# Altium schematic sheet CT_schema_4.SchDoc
size 604 x 419 mm
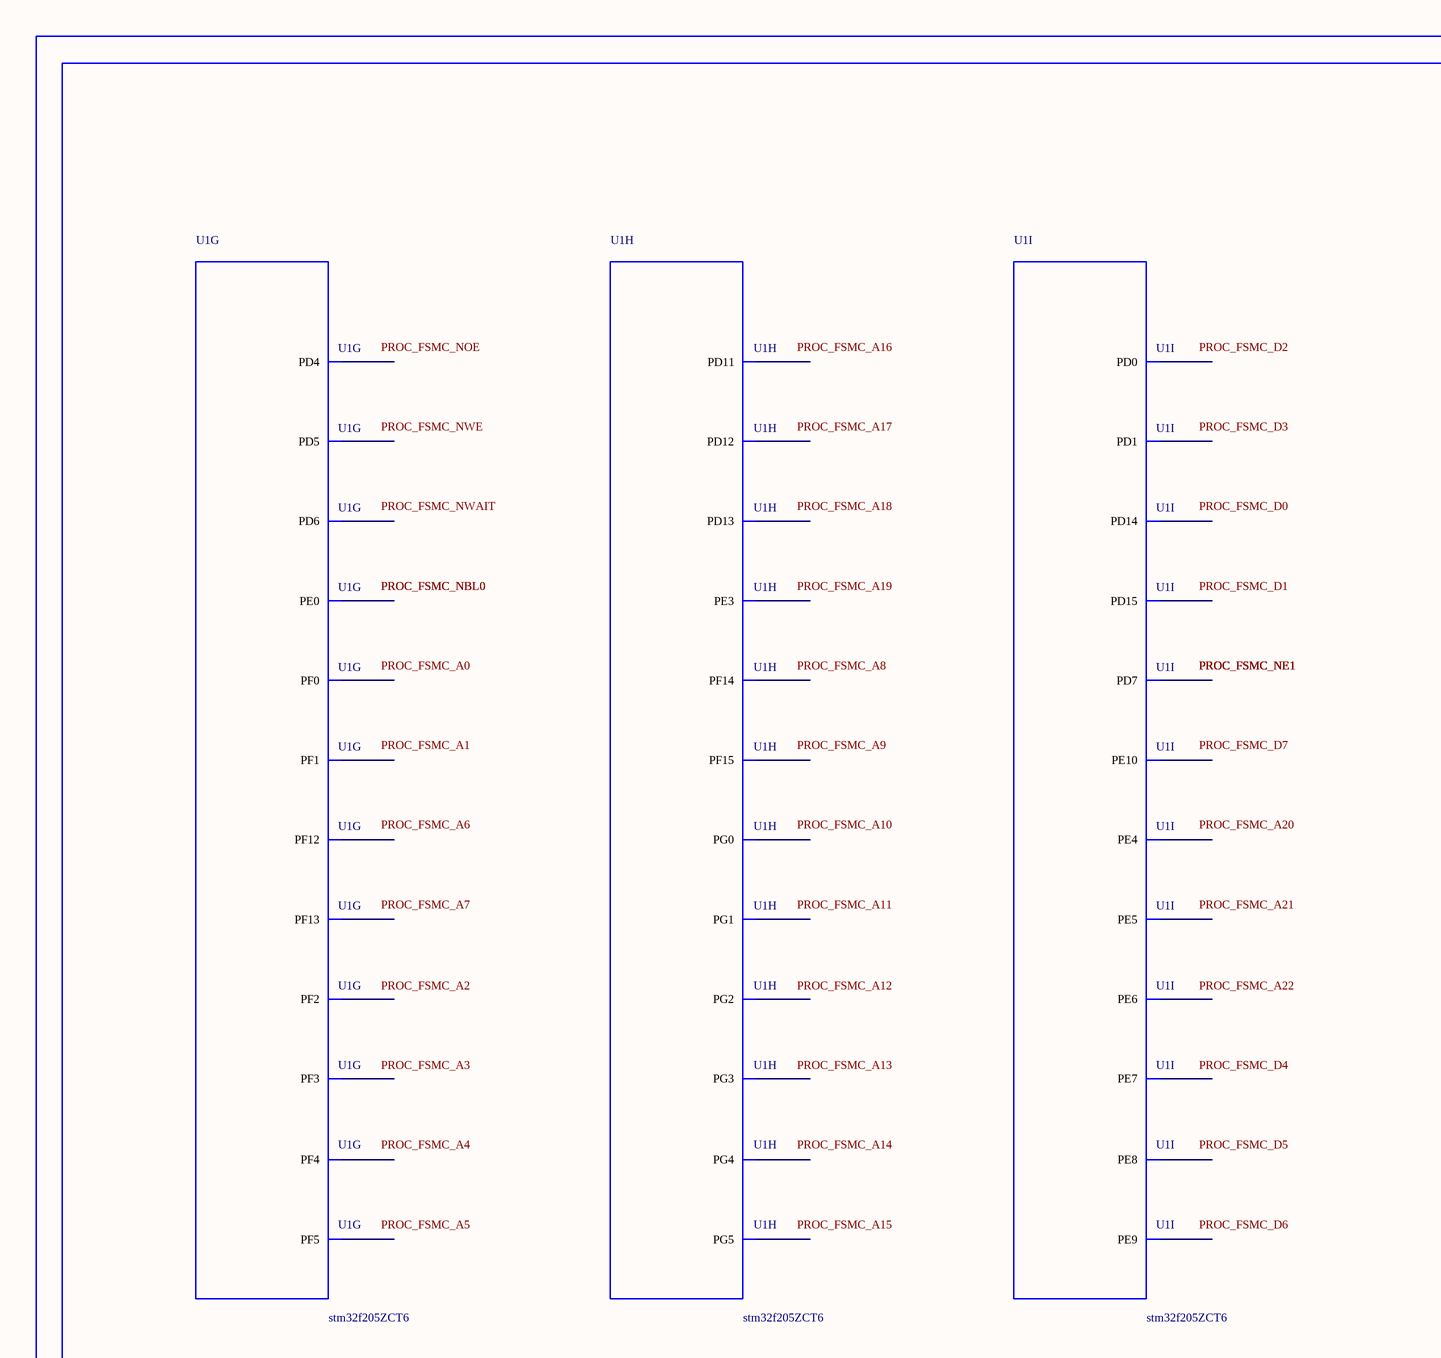
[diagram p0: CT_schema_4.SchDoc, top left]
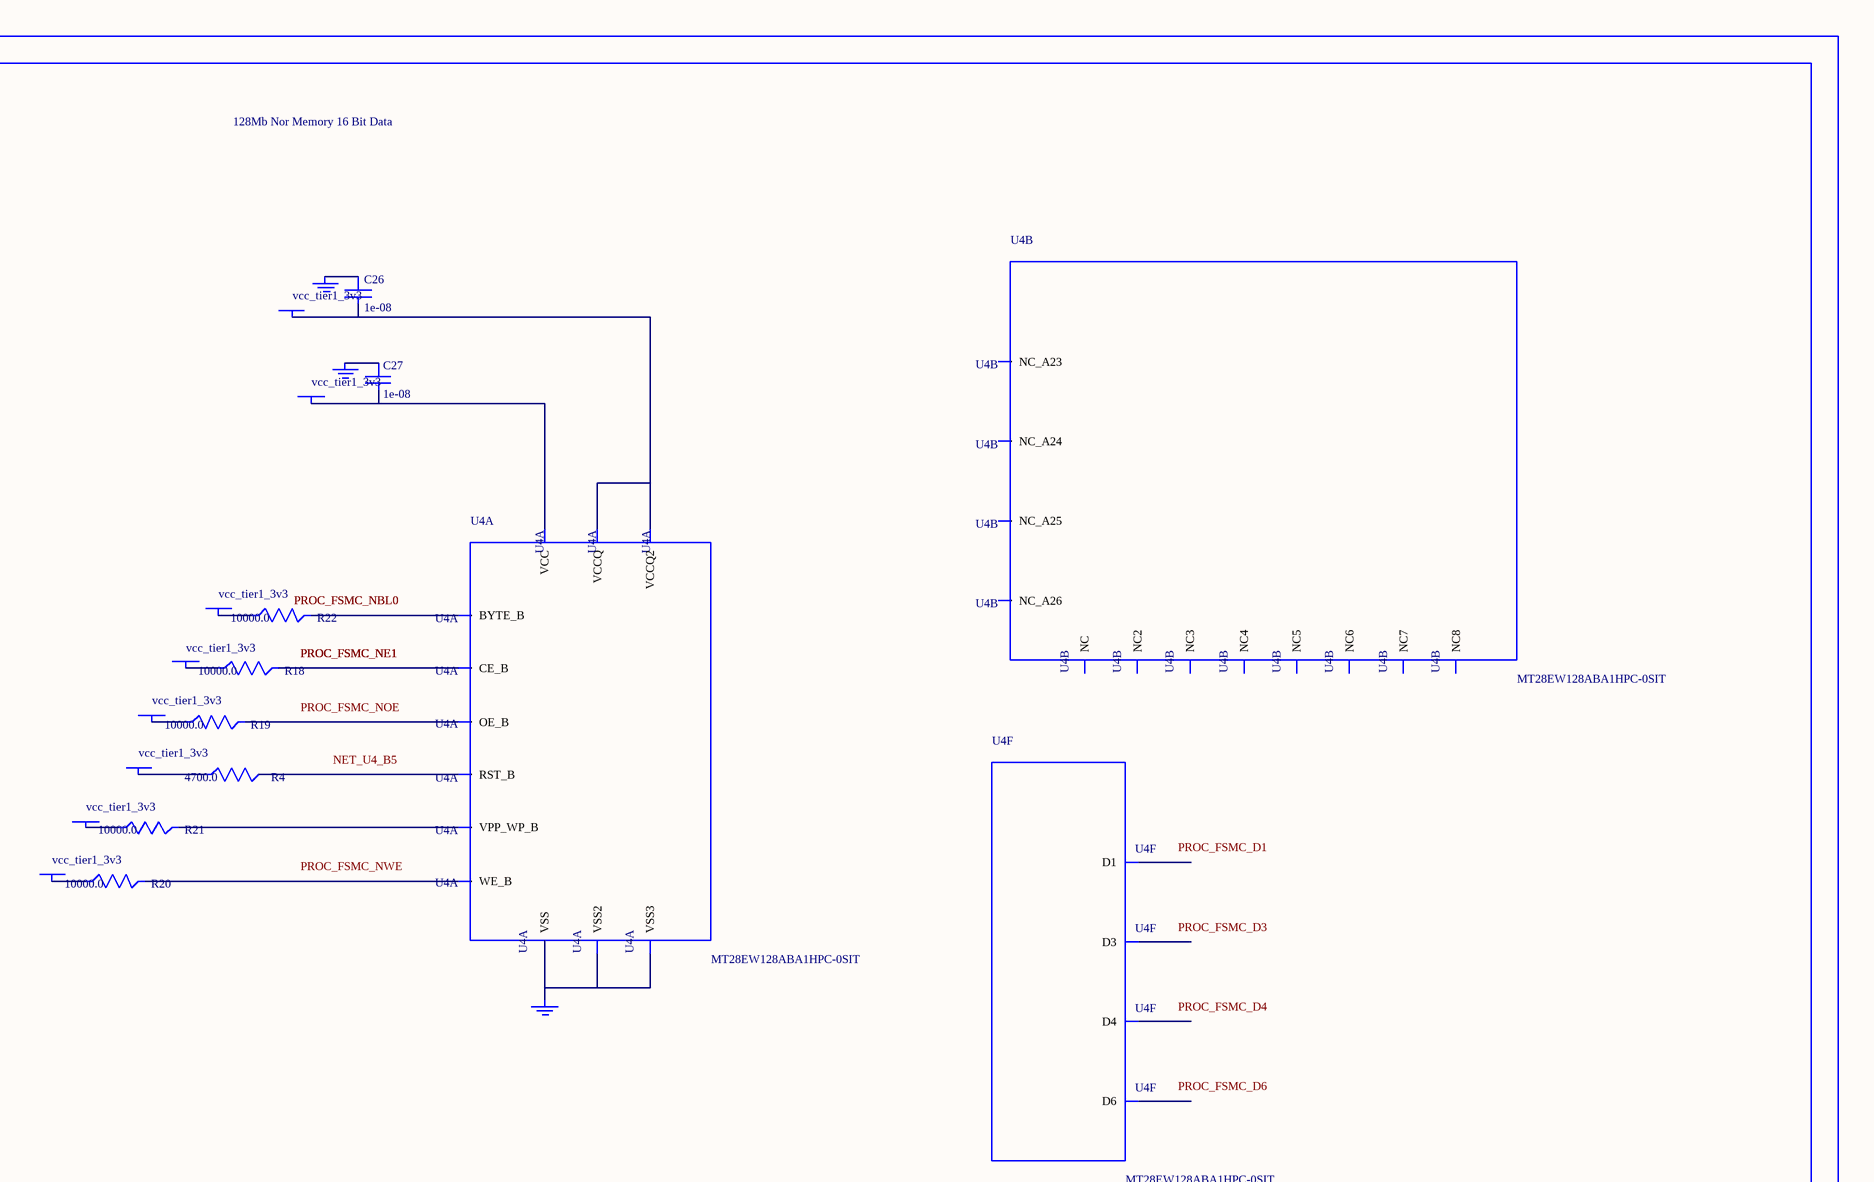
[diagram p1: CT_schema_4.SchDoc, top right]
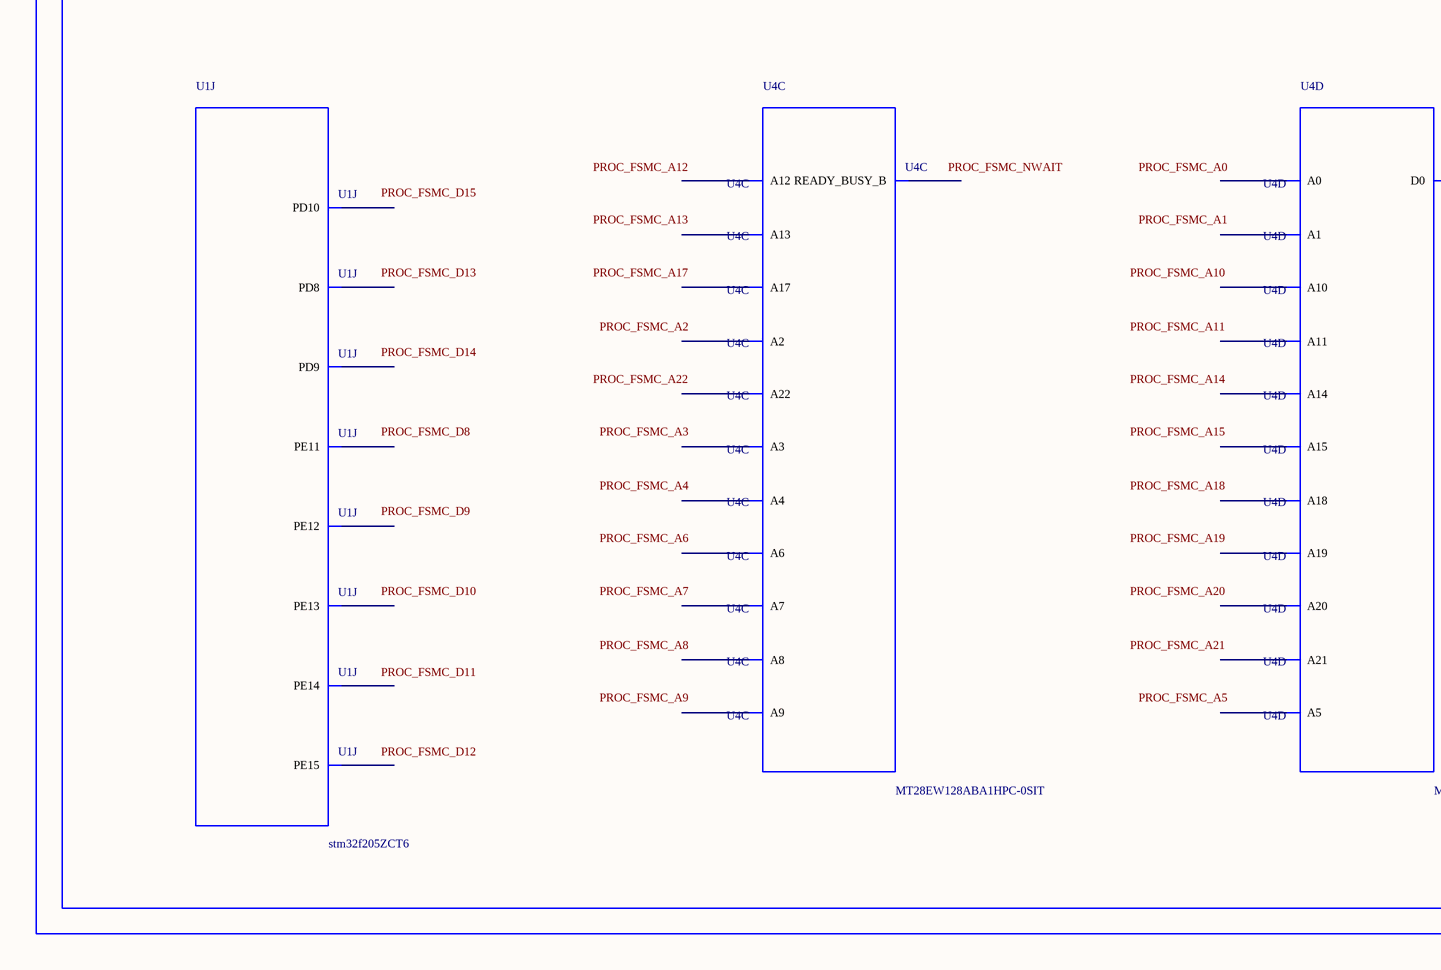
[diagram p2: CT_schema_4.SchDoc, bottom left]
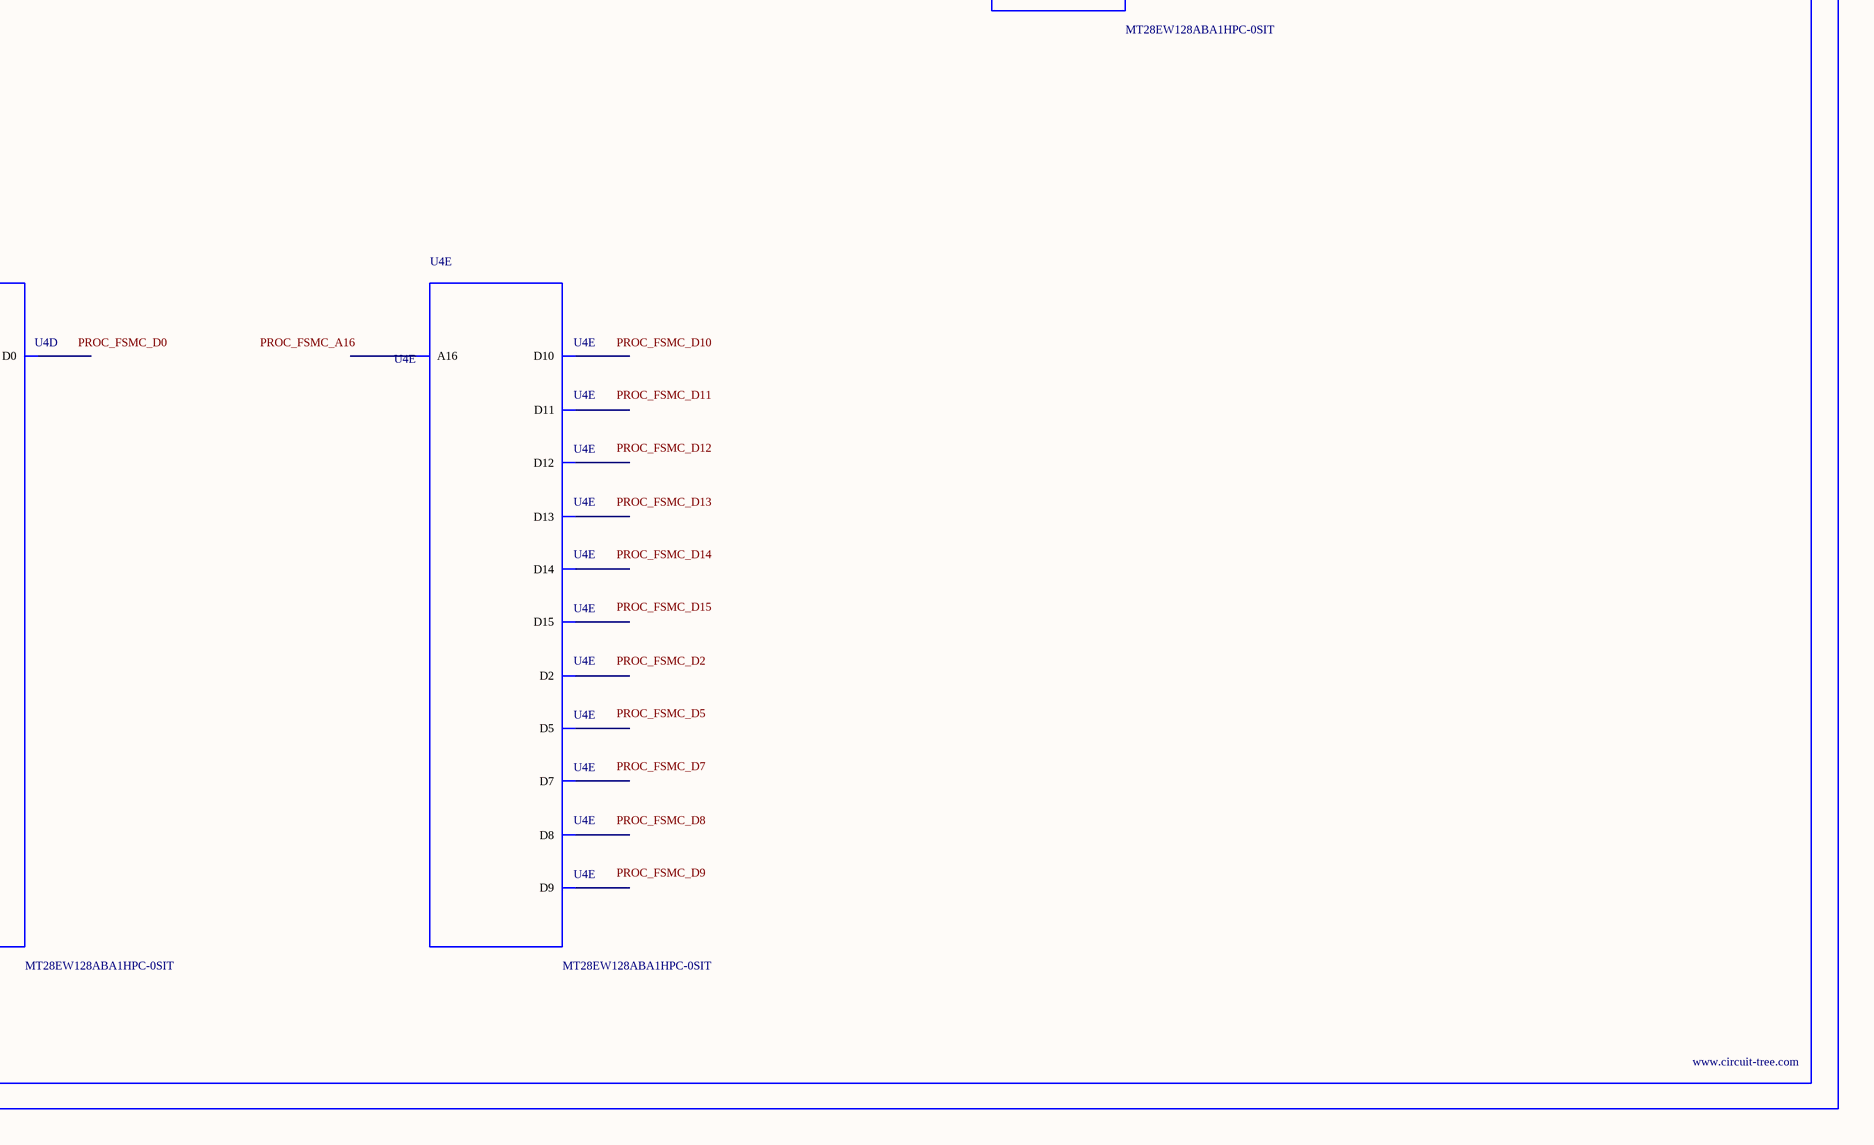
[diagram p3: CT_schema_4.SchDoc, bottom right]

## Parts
BORDER3  (no value)
C26  1e-08  [C0402]
C27  1e-08  [C0402]
GND_INSTANCE_3_0  (no value)
GND_INSTANCE_3_1  (no value)
GND_INSTANCE_3_2  (no value)
POWER_INSTANCE_3_0  vcc_tier1_3v3
POWER_INSTANCE_3_1  vcc_tier1_3v3
POWER_INSTANCE_3_2  vcc_tier1_3v3
POWER_INSTANCE_3_3  vcc_tier1_3v3
POWER_INSTANCE_3_4  vcc_tier1_3v3
POWER_INSTANCE_3_5  vcc_tier1_3v3
POWER_INSTANCE_3_6  vcc_tier1_3v3
POWER_INSTANCE_3_7  vcc_tier1_3v3
R4  4700.0  [R0603]
R18  10000.0  [R0603]
R19  10000.0  [R0603]
R20  10000.0  [R0603]
R21  10000.0  [R0603]
R22  10000.0  [R0603]
U1  stm32f205ZCT6  [LQFP144]  (parts G,H,I,J of 12)
U4  MT28EW128ABA1HPC-0SIT  [LBGA-64]  (parts A,B,C,D,E,F of 6)

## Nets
NetC26_1: C26.1 GND_INSTANCE_3_0.0(GND)
NetC26_2: C26.2 POWER_INSTANCE_3_0.0(PWR) U4.D8(VCCQ) U4.F1(VCCQ2)
NetC27_1: C27.1 GND_INSTANCE_3_1.0(GND)
NetC27_2: C27.2 POWER_INSTANCE_3_1.0(PWR) U4.G5(VCC)
NetGND_INSTANCE_3_2_0: GND_INSTANCE_3_2.0(GND) U4.E8(VSS) U4.H2(VSS2) U4.H7(VSS3)
NetPOWER_INSTANCE_3_2_0: POWER_INSTANCE_3_2.0(PWR) R18.1
NetPOWER_INSTANCE_3_3_0: POWER_INSTANCE_3_3.0(PWR) R19.1
NetPOWER_INSTANCE_3_4_0: POWER_INSTANCE_3_4.0(PWR) R20.1
NetPOWER_INSTANCE_3_5_0: POWER_INSTANCE_3_5.0(PWR) R21.1
NetPOWER_INSTANCE_3_6_0: POWER_INSTANCE_3_6.0(PWR) R22.1
NetPOWER_INSTANCE_3_7_0: POWER_INSTANCE_3_7.0(PWR) R4.1
NetR4_2: R4.2 U4.B5(RST_B)
NetR18_2: R18.2 U4.F2(CE_B)
NetR19_2: R19.2 U4.G2(OE_B)
NetR20_2: R20.2 U4.A5(WE_B)
NetR21_2: R21.2 U4.B4(VPP_WP_B)
NetR22_2: R22.2 U4.F7(BYTE_B)

Not connected (* = marked no-connect by the designer): U1 2(PE3) 3(PE4) 4(PE5) 5(PE6) 10(PF0) 11(PF1) 12(PF2) 13(PF3) 14(PF4) 15(PF5) 50(PF12) 53(PF13) 54(PF14) 55(PF15) 56(PG0) 57(PG1) 58(PE7) 59(PE8) 60(PE9) 63(PE10) 64(PE11) 65(PE12) 66(PE13) 67(PE14) 68(PE15) 77(PD8) 78(PD9) 79(PD10) 80(PD11) 81(PD12) 82(PD13) 85(PD14) 86(PD15) 87(PG2) 88(PG3) 89(PG4) 90(PG5) 114(PD0) 115(PD1) 118(PD4) 119(PD5) 122(PD6) 123(PD7) 141(PE0); U4 A1(NC) A2(A3) A3(A7) A4(READY_BUSY_B) A6(A9) A7(A13) A8(NC2) B1(NC_A26) B2(A4) B3(A17) B6(A8) B7(A12) B8(A22) C1(NC3) C2(A2) C3(A6) C4(A18) C5(A21) C6(A10) C7(A14) C8(NC_A23) D1(NC4) D2(A1) D3(A5) D4(A20) D5(A19) D6(A11) D7(A15) E1(NC5) E2(A0) E3(D0) E4(D2) E5(D5) E6(D7) E7(A16) F3(D8) F4(D10) F5(D12) F6(D14) F8(NC_A24) G1(NC6) G3(D9) G4(D11) G6(D13) G7(D15) G8(NC_A25) H1(NC7) H3(D1) H4(D3) H5(D4) H6(D6) H8(NC8)

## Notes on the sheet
- Labels drawn without touching a wire or pin: NET_U4_B5, PROC_FSMC_A0, PROC_FSMC_A1, PROC_FSMC_A2, PROC_FSMC_A3, PROC_FSMC_A4, PROC_FSMC_A5, PROC_FSMC_A6, PROC_FSMC_A7, PROC_FSMC_A8, PROC_FSMC_A9, PROC_FSMC_A10, PROC_FSMC_A11, PROC_FSMC_A12, PROC_FSMC_A13, PROC_FSMC_A14, PROC_FSMC_A15, PROC_FSMC_A16, PROC_FSMC_A17, PROC_FSMC_A18, PROC_FSMC_A19, PROC_FSMC_A20, PROC_FSMC_A21, PROC_FSMC_A22, PROC_FSMC_D0, PROC_FSMC_D1, PROC_FSMC_D2, PROC_FSMC_D3, PROC_FSMC_D4, PROC_FSMC_D5, PROC_FSMC_D6, PROC_FSMC_D7, PROC_FSMC_D8, PROC_FSMC_D9, PROC_FSMC_D10, PROC_FSMC_D11, PROC_FSMC_D12, PROC_FSMC_D13, PROC_FSMC_D14, PROC_FSMC_D15, PROC_FSMC_NOE, PROC_FSMC_NWAIT, PROC_FSMC_NWE

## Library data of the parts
BORDER3 = BORDER_PAGE3
C26 C27 = C0402C103K3RAC
GND_INSTANCE_3_0-GND_INSTANCE_3_2 = GND
POWER_INSTANCE_3_0-POWER_INSTANCE_3_7 = PWR
R4 = RC0603JR-074K7L
R18-R22 = RC0603JR-0710KL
